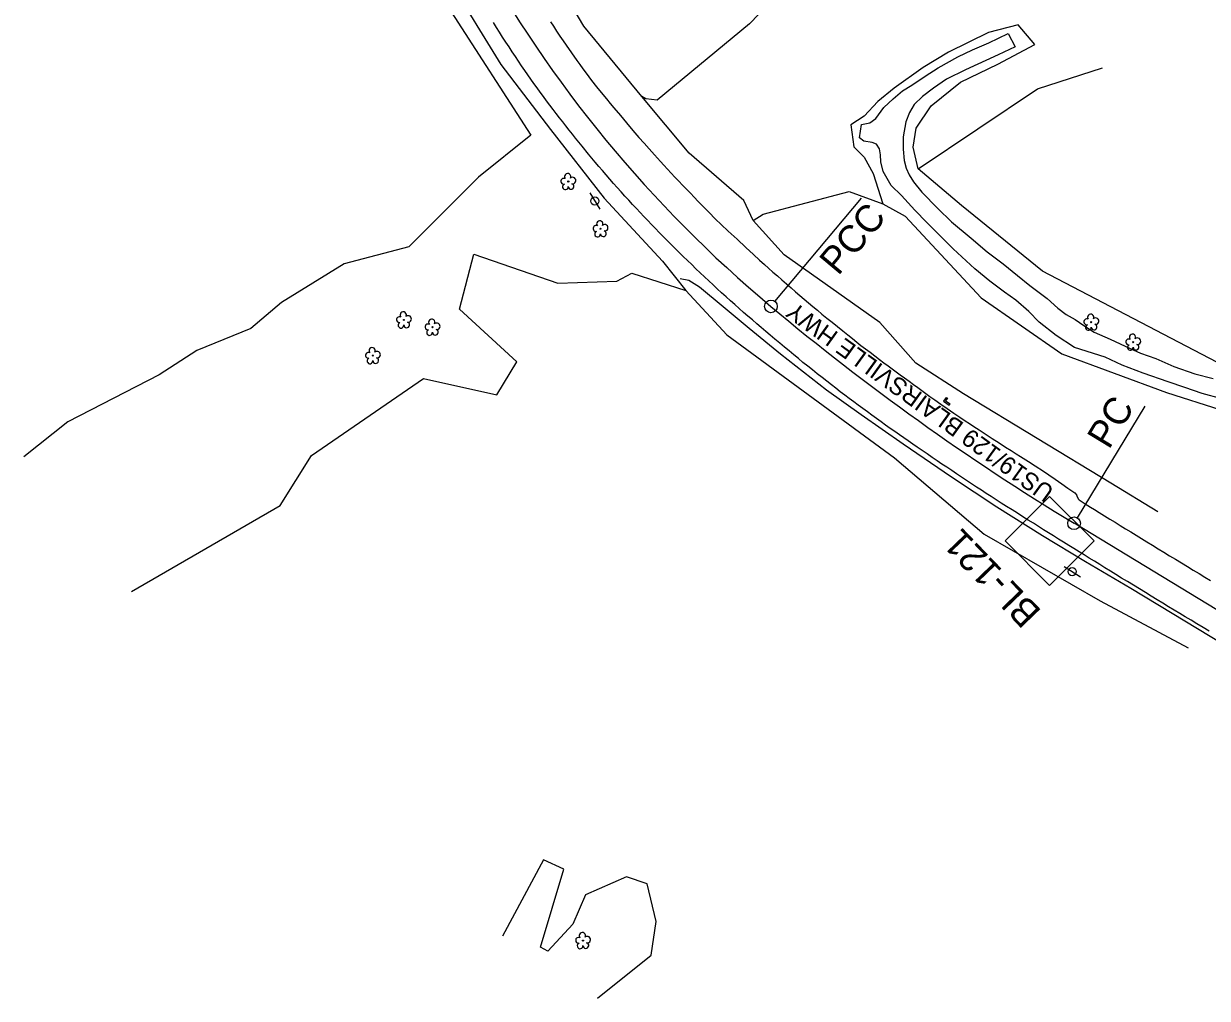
# Model space of a CAD drawing. Extents: x 473158 to 477500, y 500738 to 505114.
# Drawn here: x 474291 to 474989, y 502743 to 503318 of the extents above; entities that cross this region are included whole.
import ezdxf

# ---------------------------------------------------------------- set-up
doc = ezdxf.new("R2010")
doc.units = 0
for name, color, linetype in [('CTL Secondary Horizontal and Vertical CELL', 7, 'Continuous'), ('CTL Secondary Horizontal and Vertical Text', 7, 'Continuous'), ('Exist Guardrail', 7, 'Continuous'), ('Exist Horizontal Alignment', 7, 'Continuous'), ('Exist Roads EOP', 7, 'Continuous'), ('Exist Roads EOP Text', 7, 'Continuous'), ('Exist Roads Soil', 7, 'Continuous'), ('Exist Structure Minor Head and End Wall', 7, 'Continuous'), ('Exist Utilities Telephone Pole CELL', 7, 'Continuous'), ('Exist Vegetation Hedge Row', 7, 'Continuous'), ('Exist Vegetation Tree CELL', 7, 'Continuous'), ('Exist Vegetation Woods Line', 7, 'Continuous')]:
    doc.layers.add(name, color=color, linetype=linetype)

msp = doc.modelspace()

# ---------------------------------------------------------------- linework, layer by layer
at = {"layer": 'CTL Secondary Horizontal and Vertical CELL'}
msp.add_line((474895.59, 503012.87), (474895.59, 503012.87), dxfattribs=at)
msp.add_lwpolyline([(474869.52, 503012.96), (474895.72, 503039.17), (474921.97, 503012.92), (474895.77, 502986.71)], close=True, dxfattribs=at)
at = {"layer": 'Exist Guardrail'}
msp.add_lwpolyline([(475115.79, 502880.86), (475093.81, 502894.53), (475063.36, 502912.74), (475035.88, 502929.45), (475010.91, 502944.41), (474990.4, 502956.68), (474968.08, 502970.09), (474943.75, 502984.87), (474916.99, 503000.7), (474891.57, 503015.94), (474864.64, 503032.77), (474837.82, 503050.6), (474809.48, 503069.89), (474784.69, 503087.26), (474764.25, 503101.88), (474737.05, 503123.11), (474718.63, 503138.15), (474703.33, 503150.95), (474689.31, 503162.58), (474683.03, 503166.54), (474677.9, 503167.41)], dxfattribs=at)
at = {"layer": 'Exist Horizontal Alignment'}
for p, q in [((474733.84, 503154.05), (474784.78, 503214.95)), ((474912.14, 503026.56), (474952.07, 503092.44)), ((475098.63, 502909.13), (474910.19, 503023.36))]:
    msp.add_line(p, q, dxfattribs=at)
for centre in [(474731.44, 503151.18), (474910.19, 503023.36)]:
    msp.add_circle(centre, 3.75, dxfattribs=at)
for centre, radius, start, end in [((475209.24, 503722.4), 744.7, 208.80885, 230.08898), ((475662.14, 504263.85), 1450.6, 230.08898, 238.77708)]:
    msp.add_arc(centre, radius, start, end, dxfattribs=at)
at = {"layer": 'Exist Roads EOP'}
for points in [[(474989.91, 502959.76), (474986.24, 502961.95), (474982.64, 502964.1), (474979.15, 502966.18), (474975.77, 502968.21), (474972.5, 502970.17), (474969.25, 502972.13), (474965.95, 502974.13), (474962.6, 502976.16), (474959.19, 502978.24), (474955.74, 502980.34), (474952.25, 502982.46), (474948.73, 502984.61), (474945.18, 502986.77), (474941.66, 502988.92), (474938.23, 502991.03), (474934.88, 502993.11), (474931.61, 502995.16), (474928.42, 502997.16), (474925.28, 502999.11), (474922.2, 503001.01), (474919.17, 503002.86), (474916.16, 503004.7), (474913.14, 503006.55), (474910.11, 503008.42), (474907.06, 503010.31), (474904.03, 503012.2), (474901.03, 503014.06), (474898.07, 503015.9), (474895.15, 503017.73), (474892.21, 503019.55), (474889.23, 503021.42), (474886.19, 503023.32), (474883.1, 503025.25), (474879.97, 503027.22), (474876.81, 503029.21), (474873.63, 503031.21), (474870.42, 503033.24), (474867.25, 503035.25), (474864.19, 503037.2), (474861.23, 503039.09), (474858.38, 503040.93), (474855.57, 503042.76), (474852.7, 503044.64), (474849.79, 503046.56), (474846.84, 503048.52), (474843.87, 503050.5), (474840.94, 503052.46), (474838.03, 503054.4), (474835.15, 503056.32), (474832.28, 503058.26), (474829.38, 503060.21), (474826.46, 503062.2), (474823.51, 503064.21), (474820.59, 503066.2), (474817.77, 503068.14), (474815.04, 503070.03), (474812.4, 503071.86), (474809.8, 503073.67), (474807.17, 503075.52), (474804.5, 503077.39), (474801.81, 503079.28), (474799.1, 503081.2), (474796.4, 503083.12), (474793.7, 503085.06), (474791.01, 503087.01), (474788.32, 503088.96), (474785.64, 503090.92), (474782.96, 503092.89), (474780.29, 503094.87), (474777.63, 503096.86), (474774.98, 503098.86), (474772.34, 503100.87), (474769.72, 503102.89), (474767.07, 503104.95), (474764.36, 503107.06), (474761.59, 503109.23), (474758.76, 503111.45), (474755.92, 503113.7), (474753.12, 503115.93), (474750.36, 503118.16), (474747.64, 503120.39), (474744.92, 503122.63), (474742.18, 503124.9), (474739.41, 503127.21), (474736.61, 503129.55), (474733.83, 503131.9), (474731.08, 503134.21), (474728.38, 503136.48), (474725.73, 503138.71), (474723.1, 503140.93), (474720.49, 503143.17), (474717.88, 503145.41), (474715.29, 503147.67), (474712.7, 503149.94), (474710.12, 503152.23), (474707.54, 503154.52), (474704.97, 503156.83), (474702.4, 503159.16), (474699.85, 503161.49), (474697.31, 503163.85), (474694.79, 503166.21), (474692.27, 503168.59), (474689.76, 503170.98), (474687.25, 503173.39), (474684.74, 503175.8), (474682.26, 503178.21), (474679.8, 503180.61), (474677.38, 503183), (474674.99, 503185.38), (474672.62, 503187.75), (474670.26, 503190.1), (474667.93, 503192.44), (474665.61, 503194.76), (474663.31, 503197.08), (474661.04, 503199.4), (474658.79, 503201.73), (474656.57, 503204.08), (474654.34, 503206.44), (474652.1, 503208.84), (474649.85, 503211.28), (474647.58, 503213.75), (474645.31, 503216.24), (474643.07, 503218.73), (474640.87, 503221.23), (474638.69, 503223.72), (474636.53, 503226.22), (474634.37, 503228.72), (474632.2, 503231.22), (474630.03, 503233.71), (474627.9, 503236.18), (474625.84, 503238.6), (474623.86, 503240.96), (474620.08, 503245.57), (474618.19, 503247.91), (474616.3, 503250.29), (474614.39, 503252.7), (474612.48, 503255.13), (474610.58, 503257.56), (474608.68, 503259.99), (474606.8, 503262.42), (474604.91, 503264.86), (474603.02, 503267.33), (474601.12, 503269.83), (474599.21, 503272.36), (474597.3, 503274.91), (474595.43, 503277.45), (474593.57, 503280), (474591.74, 503282.54), (474589.92, 503285.11), (474588.1, 503287.7), (474586.28, 503290.33), (474584.47, 503292.99), (474582.64, 503295.69), (474580.79, 503298.44), (474578.92, 503301.25), (474577.02, 503304.12), (474575.13, 503307.02), (474573.26, 503309.91), (474571.42, 503312.79), (474569.61, 503315.68), (474567.8, 503318.58)], [(474601.42, 503318.98), (474603.21, 503316.28), (474605.07, 503313.47), (474607.02, 503310.57), (474608.95, 503307.73), (474610.73, 503305.12), (474613.88, 503300.57), (474617, 503296.17), (474618.75, 503293.75), (474620.62, 503291.17), (474622.49, 503288.64), (474625.75, 503284.29), (474628.6, 503280.64), (474632.27, 503276.16), (474634.49, 503273.51), (474636.76, 503270.8), (474638.89, 503268.25), (474642.72, 503263.65), (474646.34, 503259.34), (474650.09, 503254.94), (474653.64, 503250.82), (474656.68, 503247.34), (474659.59, 503244.06), (474662.76, 503240.55), (474666.33, 503236.64), (474668.32, 503234.46), (474670.44, 503232.14), (474672.65, 503229.75), (474674.87, 503227.37), (474677.11, 503224.99), (474679.38, 503222.63), (474681.66, 503220.26), (474683.95, 503217.88), (474686.24, 503215.5), (474688.55, 503213.11), (474690.79, 503210.79), (474694.84, 503206.64), (474698.86, 503202.6), (474702.07, 503199.52), (474706.26, 503195.56), (474711.45, 503190.72), (474716.72, 503185.84), (474721.17, 503181.73), (474724.81, 503178.41), (474727.64, 503175.86), (474730.1, 503173.68), (474732.63, 503171.44), (474735.25, 503169.13), (474737.95, 503166.77), (474740.66, 503164.4), (474743.31, 503162.08), (474745.91, 503159.83), (474748.45, 503157.64), (474750.98, 503155.47), (474753.55, 503153.29), (474756.17, 503151.09), (474758.82, 503148.89), (474761.56, 503146.63), (474764.45, 503144.27), (474767.47, 503141.82), (474770.63, 503139.26), (474773.76, 503136.74), (474776.71, 503134.38), (474779.46, 503132.2), (474782.03, 503130.18), (474784.54, 503128.22), (474787.16, 503126.21), (474789.87, 503124.14), (474792.69, 503122.02), (474795.47, 503119.93), (474798.11, 503117.96), (474800.6, 503116.11), (474805.27, 503112.67), (474807.71, 503110.89), (474810.27, 503109.03), (474812.94, 503107.1), (474815.6, 503105.17), (474818.12, 503103.33), (474822.78, 503099.91), (474825.22, 503098.13), (474828.15, 503096.03), (474831.56, 503093.63), (474835.46, 503090.91), (474839.39, 503088.2), (474842.87, 503085.83), (474845.92, 503083.78), (474848.52, 503082.07), (474851.14, 503080.36), (474854.24, 503078.34), (474857.83, 503076), (474861.9, 503073.35), (474866.02, 503070.68), (474869.74, 503068.28), (474873.07, 503066.15), (474876.01, 503064.29), (474878.65, 503062.62), (474883.33, 503059.68), (474887.23, 503057.22), (474892.15, 503054.01), (474895.35, 503051.85), (474899.09, 503049.3), (474902.95, 503046.63), (474906.53, 503044.1), (474910.56, 503041.19), (474911.55, 503040.15), (474911.67, 503039.99), (474911.79, 503039.79), (474911.91, 503039.56), (474912.43, 503038.16), (474912.53, 503037.98), (474912.66, 503037.8), (474912.81, 503037.63), (474913.27, 503037.22), (474916.81, 503034.8), (474919.84, 503032.9), (474922.17, 503031.45), (474925.05, 503029.67), (474928.18, 503027.74), (474931.3, 503025.82), (474934.39, 503023.92), (474937.46, 503022.04), (474940.53, 503020.16), (474943.64, 503018.26), (474946.77, 503016.33), (474949.94, 503014.37), (474953.15, 503012.39), (474956.41, 503010.38), (474959.73, 503008.35), (474963.11, 503006.3), (474966.52, 503004.22), (474969.97, 503002.13), (474973.46, 503000.01), (474976.97, 502997.88), (474980.48, 502995.75), (474983.93, 502993.66), (474987.32, 502991.6), (474990.65, 502989.58)]]:
    msp.add_lwpolyline(points, dxfattribs=at)
at = {"layer": 'Exist Roads Soil'}
msp.add_lwpolyline([(474997.32, 503096.78), (474985.68, 503099.85), (474975.52, 503103.38), (474965.59, 503106.63), (474950.95, 503111.75), (474938.58, 503116.56), (474928.51, 503121.22), (474910.45, 503126.93), (474899.61, 503134.1), (474889.66, 503141.85), (474883.57, 503148.24), (474875.85, 503154.91), (474869.18, 503159.63), (474860.58, 503166.07), (474851.6, 503173.42), (474838.93, 503185.19), (474823.4, 503200.56), (474816.32, 503207.87), (474808.48, 503216.62), (474802.43, 503222.37), (474797.67, 503230.8), (474796.25, 503236.31), (474795.97, 503240.45), (474795.5, 503244.08), (474793.7, 503246.75), (474791.14, 503247.7), (474786.22, 503248.65), (474783.71, 503250.57), (474784.79, 503258.31), (474789.77, 503259.35), (474793.33, 503261.93), (474798.07, 503268.34), (474803.47, 503273.46), (474809.03, 503278.19), (474814.55, 503281.69), (474822.36, 503286.84), (474830.05, 503291.85), (474841.7, 503298.39), (474850.25, 503302.35), (474859.84, 503306.51), (474871.36, 503312.1), (474875.54, 503304.21), (474865.38, 503299.53), (474846.16, 503290.73), (474834.95, 503285.05), (474827.33, 503279.81), (474820.82, 503274.86), (474815.81, 503270.24), (474813.1, 503265.46), (474810.9, 503260.03), (474809.39, 503251.17), (474809.41, 503243.85), (474810.02, 503237.27), (474811.17, 503232.69), (474812.99, 503228.69), (474815.42, 503224.57), (474820.52, 503218.48), (474829.85, 503208.9), (474837.9, 503201.07), (474849.52, 503191.46), (474859, 503183.38), (474868.36, 503176.31), (474876.8, 503169.44), (474884.06, 503163.58), (474889.68, 503159.41), (474894.3, 503155.81), (474900.61, 503150.08), (474905.57, 503146.46), (474910.84, 503143.5), (474915.87, 503139.99), (474922.06, 503136.01), (474931.46, 503131.92), (474940.24, 503127.74), (474949.36, 503123.55), (474958.4, 503120.46), (474969.01, 503115.79), (474981.33, 503111.42), (474992.13, 503108.66)], dxfattribs=at)
at = {"layer": 'Exist Structure Minor Head and End Wall'}
for p, q in [((474834.83, 503097.52), (474835.5, 503097.02)), ((474836.59, 503093.02), (474837.07, 503093.7))]:
    msp.add_line(p, q, dxfattribs=at)
for points in [[(474834.83, 503097.52), (474833.27, 503095.4), (474836.59, 503093.02)], [(474835.5, 503097.02), (474834.44, 503095.58), (474837.07, 503093.7)]]:
    msp.add_lwpolyline(points, dxfattribs=at)
at = {"layer": 'Exist Utilities Telephone Pole CELL'}
for p, q in [((474624.67, 503218.12), (474630.62, 503208.47)), ((474627.65, 503213.29), (474627.65, 503213.29)), ((474904.28, 502997.82), (474913.9, 502991.82)), ((474909.09, 502994.82), (474909.09, 502994.82))]:
    msp.add_line(p, q, dxfattribs=at)
for centre in [(474627.65, 503213.29), (474909.09, 502994.82)]:
    msp.add_circle(centre, 2.41, dxfattribs=at)
at = {"layer": 'Exist Vegetation Hedge Row'}
msp.add_line((474683.33, 503241.56), (474655.3, 503274.92), dxfattribs=at)
for points in [[(474444.08, 503695.01), (474448.37, 503644.42), (474453.53, 503599.09), (474463.11, 503545.53), (474470.08, 503520.03), (474486.91, 503462.77), (474502.84, 503421.03), (474519.79, 503383.9), (474541.73, 503343.5), (474572.12, 503293.76), (474601.46, 503255.5), (474633.21, 503214.89)], [(474818.2, 503232.27), (474815.22, 503245.09), (474817.1, 503256.25), (474826.02, 503269.43), (474843.24, 503283.27), (474865.23, 503293.93), (474887.15, 503305.55), (474877.22, 503317.13), (474859.83, 503312.62), (474836.16, 503301.13), (474821.18, 503292.07), (474804.15, 503279.9), (474794.49, 503272), (474786.36, 503263.31), (474778.49, 503258.26), (474780.27, 503245.3), (474786.4, 503239.19), (474791.79, 503229.44), (474797.52, 503211.74)], [(474721.03, 503201.76), (474715.57, 503213.51), (474683.33, 503241.56)], [(474633.21, 503214.89), (474667.54, 503177.92), (474681.2, 503160.59)]]:
    msp.add_lwpolyline(points, dxfattribs=at)
at = {"layer": 'Exist Vegetation Tree CELL'}
for p, q in [((474611.98, 503224.79), (474611.98, 503224.79)), ((474630.93, 503196.94), (474630.93, 503196.94)), ((474515.05, 503143.22), (474515.05, 503143.22)), ((474531.89, 503138.91), (474531.89, 503138.91)), ((474920.33, 503141.91), (474920.33, 503141.91)), ((474945.04, 503130.08), (474945.04, 503130.08)), ((474496.73, 503122.19), (474496.73, 503122.19)), ((474620.66, 502777.36), (474620.66, 502777.36))]:
    msp.add_line(p, q, dxfattribs=at)
for centre in [(474611.98, 503224.79), (474630.93, 503196.94), (474515.05, 503143.22), (474531.89, 503138.91), (474920.33, 503141.91), (474945.04, 503130.08), (474496.73, 503122.19), (474620.66, 502777.36)]:
    msp.add_circle(centre, 0.326, dxfattribs=at)
for centre, radius, start, end in [((474611.6, 503227.67), 1.86, 330.16508, 219.71335), ((474614.53, 503225.38), 1.9, 257.1011, 134.19993), ((474609.38, 503224.95), 1.73, 62.66361, 279.3457), ((474610.28, 503221.67), 1.69, 111.56708, 6.23104), ((474613.66, 503221.89), 1.7, 181.28216, 74.55999), ((474630.54, 503199.81), 1.86, 330.16508, 219.71335), ((474633.48, 503197.53), 1.9, 257.1011, 134.19993), ((474628.32, 503197.09), 1.73, 62.66361, 279.3457), ((474629.22, 503193.82), 1.69, 111.56708, 6.23104), ((474632.6, 503194.04), 1.7, 181.28216, 74.55999), ((474512.45, 503143.38), 1.73, 62.66361, 279.3457), ((474514.67, 503146.1), 1.86, 330.16508, 219.71335), ((474517.6, 503143.81), 1.9, 257.1011, 134.19993), ((474531.5, 503141.79), 1.86, 330.16508, 219.71335), ((474917.73, 503142.07), 1.73, 62.66361, 279.3457), ((474919.95, 503144.79), 1.86, 330.16508, 219.71335), ((474922.88, 503142.5), 1.9, 257.1011, 134.19993), ((474513.35, 503140.1), 1.69, 111.56708, 6.23104), ((474516.72, 503140.32), 1.7, 181.28216, 74.55999), ((474529.28, 503139.07), 1.73, 62.66361, 279.3457), ((474530.18, 503135.79), 1.69, 111.56708, 6.23104), ((474533.56, 503136.01), 1.7, 181.28216, 74.55999), ((474534.44, 503139.5), 1.9, 257.1011, 134.19993), ((474918.63, 503138.79), 1.69, 111.56708, 6.23104), ((474922.01, 503139.01), 1.7, 181.28216, 74.55999), ((474942.44, 503130.23), 1.73, 62.66361, 279.3457), ((474944.66, 503132.95), 1.86, 330.16508, 219.71335), ((474947.59, 503130.67), 1.9, 257.1011, 134.19993), ((474494.13, 503122.34), 1.73, 62.66361, 279.3457), ((474496.35, 503125.06), 1.86, 330.16508, 219.71335), ((474499.28, 503122.77), 1.9, 257.1011, 134.19993), ((474943.34, 503126.96), 1.69, 111.56708, 6.23104), ((474946.72, 503127.18), 1.7, 181.28216, 74.55999), ((474495.03, 503119.06), 1.69, 111.56708, 6.23104), ((474498.4, 503119.29), 1.7, 181.28216, 74.55999), ((474620.27, 502780.23), 1.86, 330.16508, 219.71335), ((474618.05, 502777.51), 1.73, 62.66361, 279.3457), ((474618.95, 502774.24), 1.69, 111.56708, 6.23104), ((474622.33, 502774.46), 1.7, 181.28216, 74.55999), ((474623.21, 502777.95), 1.9, 257.1011, 134.19993)]:
    msp.add_arc(centre, radius, start, end, dxfattribs=at)
at = {"layer": 'Exist Vegetation Woods Line'}
for points in [[(474808.93, 503408.32), (474802.62, 503406.43), (474779.61, 503372.89), (474751.89, 503352.19), (474718.75, 503317.67), (474664.37, 503272.8), (474657.63, 503273.56), (474655.3, 503274.92), (474621.17, 503316.29), (474582.13, 503382.19), (474557.68, 503427.09), (474553.06, 503442.52), (474567.39, 503479.54), (474553.83, 503508.83), (474557.7, 503516.31), (474598.96, 503578.51), (474595.47, 503623.36), (474569.88, 503626.18), (474569.75, 503604.61), (474555.47, 503601.48), (474547.44, 503629.91), (474546.56, 503674.1)], [(474417.41, 503659.72), (474425.49, 503589.6), (474446.84, 503556.89), (474463.81, 503473.01), (474471.33, 503431.8), (474489.58, 503404.95), (474518.23, 503357.05), (474542.86, 503324.75), (474589.83, 503252.15), (474559.03, 503227.36), (474517.97, 503186.35), (474479.83, 503176.32), (474442.79, 503153.41), (474424.74, 503138.06), (474392.94, 503125.22), (474370.72, 503110.81), (474316.94, 503083.12), (474290.87, 503062.45)], [(474818.2, 503232.27), (474888.55, 503279.47), (474926.88, 503291.72)], [(475230.74, 502956.28), (475224.23, 502981.44), (475190.08, 503060.84), (475160.08, 503099.98), (475118.98, 503131.59), (475068.87, 503108.51), (475065.61, 503115.38), (475072.91, 503165.78), (475056.48, 503173.08), (475038.73, 503140.56), (475015.88, 503136.4), (475017.52, 503123.45), (475039.78, 503110.89), (475040.49, 503102.56), (474994.31, 503118.33), (474891.59, 503171.92), (474843.84, 503210.58), (474818.2, 503232.27)], [(474721.03, 503201.76), (474726.93, 503205.62), (474777.53, 503218.87), (474797.52, 503211.74), (474810.54, 503204.36), (474855.4, 503156.33), (474903.01, 503123.3), (474964.67, 503100.45), (475028.79, 503079.9), (475066.1, 503057.4), (475087.57, 503072.04), (475116.81, 503080.55), (475154.47, 503055.63), (475189.77, 502995.25), (475190.23, 502942), (475172.13, 502894.97), (475149.76, 502909.51)], [(474739.17, 503181.62), (474721.03, 503201.76)], [(474354.5, 502983.1), (474442, 503033.81), (474460.64, 503063.21), (474526.65, 503108.74), (474569.79, 503099), (474581.67, 503118.47), (474547.74, 503149.58), (474556.25, 503181.9), (474605.73, 503164.93), (474640.58, 503166.06), (474649.51, 503170.76), (474681.2, 503160.59), (474705.38, 503134.48), (474804.29, 503062), (474857.11, 503016.88), (474925.62, 502977.53), (474977.36, 502949.99)], [(474959.64, 503030.03), (474931.86, 503047.04), (474844.91, 503099.63), (474816.91, 503117.63), (474795.66, 503141.63), (474739.17, 503181.62)], [(474629.19, 502743.31), (474660.86, 502768.83), (474663.83, 502788.62), (474658.45, 502810.72), (474646.37, 502815), (474622.2, 502804.25), (474614.73, 502787.04), (474599.95, 502771.07), (474595.53, 502773.49), (474609.36, 502819.45), (474597.36, 502825.02), (474573.16, 502779.86)]]:
    msp.add_lwpolyline(points, dxfattribs=at)

# ---------------------------------------------------------------- texts
at = {"layer": 'CTL Secondary Horizontal and Vertical Text'}
msp.add_text('BL-121', height=16, rotation=133.87228, dxfattribs=at).set_placement((474891.53, 502971.5))
at = {"layer": 'Exist Horizontal Alignment'}
for s, rotation, p in [('PCC', 50.08898, (474771.1, 503168.82)), ('PC', 58.77708, (474930.76, 503066.33))]:
    msp.add_text(s, height=16, rotation=rotation, dxfattribs=at).set_placement(p)
at = {"layer": 'Exist Roads EOP Text'}
msp.add_text('US19/129 BLAIRSVILLE HWY', height=10.4, rotation=144.22034, dxfattribs=at).set_placement((474899.15, 503043.61))

doc.saveas('drawing.dxf')
